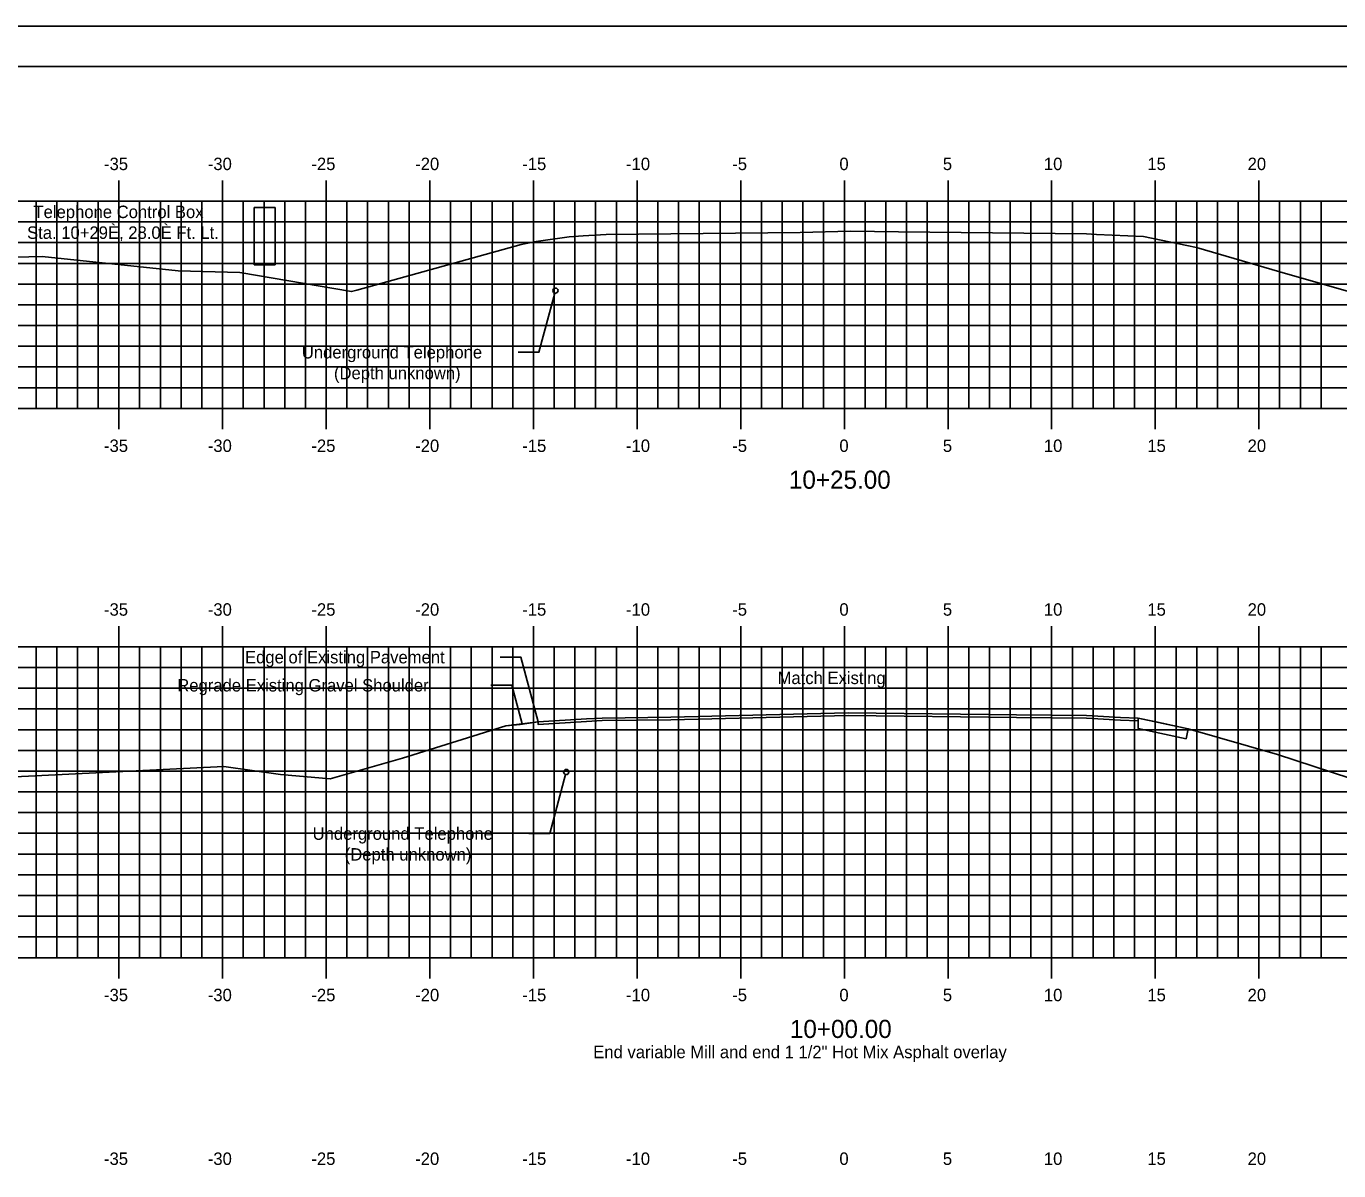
# Model space of a CAD drawing. Extents: x 2194738 to 2195190, y 863888 to 863998.
# Drawn here: x 2194880.8 to 2194944.1, y 863943.2 to 863998.4 of the extents above; entities that cross this region are included whole.
import ezdxf

# ---------------------------------------------------------------- set-up
doc = ezdxf.new("R2010")
doc.units = 0
for name, color, linetype in [('ANNOTATION', 7, 'Continuous'), ('BORDER', 7, 'Continuous'), ('H_V ANNOTATION', 7, 'Continuous'), ('MAJOR', 7, 'Continuous'), ('MINOR', 7, 'Continuous'), ('PLOT BOUNDARY', 7, 'Continuous'), ('S_Roadway_Centerline', 7, 'Continuous'), ('S_Utilities_Pole_Power', 7, 'Continuous'), ('TEMPLATE', 7, 'Continuous')]:
    doc.layers.add(name, color=color, linetype=linetype)

msp = doc.modelspace()

# ---------------------------------------------------------------- linework, layer by layer
at = {"layer": 'ANNOTATION'}
for points in [[(2194904.52, 863982.658), (2194905.52, 863982.658), (2194906.284, 863985.512)], [(2194903.646, 863967.946), (2194904.646, 863967.946), (2194904.646, 863967.946), (2194905.482, 863964.826)], [(2194903.204, 863966.589), (2194904.204, 863966.589), (2194904.204, 863966.589), (2194904.703, 863964.727)], [(2194905.04, 863959.432), (2194906.04, 863959.432), (2194906.804, 863962.286)]]:
    msp.add_lwpolyline(points, dxfattribs=at)
at = {"layer": 'BORDER'}
msp.add_lwpolyline([(2194845.256, 863891.446), (2195005.256, 863891.446), (2195005.256, 863996.446), (2194845.256, 863996.446)], close=True, dxfattribs=at)
at = {"layer": 'MAJOR'}
for p, q in [((2194885.256, 863990.948), (2194885.256, 863989.946)), ((2194890.256, 863990.948), (2194890.256, 863989.946)), ((2194895.256, 863990.948), (2194895.256, 863989.946)), ((2194900.256, 863990.948), (2194900.256, 863989.946)), ((2194905.256, 863990.948), (2194905.256, 863989.946)), ((2194910.256, 863990.948), (2194910.256, 863989.946)), ((2194915.256, 863990.948), (2194915.256, 863989.946)), ((2194920.256, 863990.948), (2194920.256, 863989.946)), ((2194925.256, 863990.948), (2194925.256, 863989.946)), ((2194930.256, 863990.948), (2194930.256, 863989.946)), ((2194935.256, 863990.948), (2194935.256, 863989.946)), ((2194940.256, 863990.948), (2194940.256, 863989.946)), ((2194850.256, 863989.946), (2194990.256, 863989.946)), ((2194885.256, 863979.946), (2194885.256, 863989.946)), ((2194890.256, 863979.946), (2194890.256, 863989.946)), ((2194895.256, 863979.946), (2194895.256, 863989.946)), ((2194900.256, 863979.946), (2194900.256, 863989.946)), ((2194905.256, 863979.946), (2194905.256, 863989.946)), ((2194910.256, 863979.946), (2194910.256, 863989.946)), ((2194915.256, 863979.946), (2194915.256, 863989.946)), ((2194920.256, 863979.946), (2194920.256, 863989.946)), ((2194925.256, 863979.946), (2194925.256, 863989.946)), ((2194930.256, 863979.946), (2194930.256, 863989.946)), ((2194935.256, 863979.946), (2194935.256, 863989.946)), ((2194940.256, 863979.946), (2194940.256, 863989.946)), ((2194850.256, 863984.946), (2194990.256, 863984.946)), ((2194850.256, 863979.946), (2194990.256, 863979.946)), ((2194885.256, 863978.944), (2194885.256, 863979.946)), ((2194890.256, 863978.944), (2194890.256, 863979.946)), ((2194895.256, 863978.944), (2194895.256, 863979.946)), ((2194900.256, 863978.944), (2194900.256, 863979.946)), ((2194905.256, 863978.944), (2194905.256, 863979.946)), ((2194910.256, 863978.944), (2194910.256, 863979.946)), ((2194915.256, 863978.944), (2194915.256, 863979.946)), ((2194920.256, 863978.944), (2194920.256, 863979.946)), ((2194925.256, 863978.944), (2194925.256, 863979.946)), ((2194930.256, 863978.944), (2194930.256, 863979.946)), ((2194935.256, 863978.944), (2194935.256, 863979.946)), ((2194940.256, 863978.944), (2194940.256, 863979.946)), ((2194885.256, 863969.448), (2194885.256, 863968.446)), ((2194890.256, 863969.448), (2194890.256, 863968.446)), ((2194895.256, 863969.448), (2194895.256, 863968.446)), ((2194900.256, 863969.448), (2194900.256, 863968.446)), ((2194905.256, 863969.448), (2194905.256, 863968.446)), ((2194910.256, 863969.448), (2194910.256, 863968.446)), ((2194915.256, 863969.448), (2194915.256, 863968.446)), ((2194920.256, 863969.448), (2194920.256, 863968.446)), ((2194925.256, 863969.448), (2194925.256, 863968.446)), ((2194930.256, 863969.448), (2194930.256, 863968.446)), ((2194935.256, 863969.448), (2194935.256, 863968.446)), ((2194940.256, 863969.448), (2194940.256, 863968.446)), ((2194850.256, 863968.446), (2194990.256, 863968.446)), ((2194885.256, 863953.446), (2194885.256, 863968.446)), ((2194890.256, 863953.446), (2194890.256, 863968.446)), ((2194895.256, 863953.446), (2194895.256, 863968.446)), ((2194900.256, 863953.446), (2194900.256, 863968.446)), ((2194905.256, 863953.446), (2194905.256, 863968.446)), ((2194910.256, 863953.446), (2194910.256, 863968.446)), ((2194915.256, 863953.446), (2194915.256, 863968.446)), ((2194920.256, 863953.446), (2194920.256, 863968.446)), ((2194925.256, 863953.446), (2194925.256, 863968.446)), ((2194930.256, 863953.446), (2194930.256, 863968.446)), ((2194935.256, 863953.446), (2194935.256, 863968.446)), ((2194940.256, 863953.446), (2194940.256, 863968.446)), ((2194850.256, 863963.446), (2194990.256, 863963.446)), ((2194850.256, 863958.446), (2194990.256, 863958.446)), ((2194850.256, 863953.446), (2194990.256, 863953.446)), ((2194885.256, 863952.444), (2194885.256, 863953.446)), ((2194890.256, 863952.444), (2194890.256, 863953.446)), ((2194895.256, 863952.444), (2194895.256, 863953.446)), ((2194900.256, 863952.444), (2194900.256, 863953.446)), ((2194905.256, 863952.444), (2194905.256, 863953.446)), ((2194910.256, 863952.444), (2194910.256, 863953.446)), ((2194915.256, 863952.444), (2194915.256, 863953.446)), ((2194920.256, 863952.444), (2194920.256, 863953.446)), ((2194925.256, 863952.444), (2194925.256, 863953.446)), ((2194930.256, 863952.444), (2194930.256, 863953.446)), ((2194935.256, 863952.444), (2194935.256, 863953.446)), ((2194940.256, 863952.444), (2194940.256, 863953.446))]:
    msp.add_line(p, q, dxfattribs=at)
at = {"layer": 'MINOR'}
for p, q in [((2194881.256, 863979.946), (2194881.256, 863989.946)), ((2194882.256, 863979.946), (2194882.256, 863989.946)), ((2194883.256, 863979.946), (2194883.256, 863989.946)), ((2194884.256, 863979.946), (2194884.256, 863989.946)), ((2194886.256, 863979.946), (2194886.256, 863989.946)), ((2194887.256, 863979.946), (2194887.256, 863989.946)), ((2194888.256, 863979.946), (2194888.256, 863989.946)), ((2194889.256, 863979.946), (2194889.256, 863989.946)), ((2194891.256, 863979.946), (2194891.256, 863989.946)), ((2194892.256, 863979.946), (2194892.256, 863989.946)), ((2194893.256, 863979.946), (2194893.256, 863989.946)), ((2194894.256, 863979.946), (2194894.256, 863989.946)), ((2194896.256, 863979.946), (2194896.256, 863989.946)), ((2194897.256, 863979.946), (2194897.256, 863989.946)), ((2194898.256, 863979.946), (2194898.256, 863989.946)), ((2194899.256, 863979.946), (2194899.256, 863989.946)), ((2194901.256, 863979.946), (2194901.256, 863989.946)), ((2194902.256, 863979.946), (2194902.256, 863989.946)), ((2194903.256, 863979.946), (2194903.256, 863989.946)), ((2194904.256, 863979.946), (2194904.256, 863989.946)), ((2194906.256, 863979.946), (2194906.256, 863989.946)), ((2194907.256, 863979.946), (2194907.256, 863989.946)), ((2194908.256, 863979.946), (2194908.256, 863989.946)), ((2194909.256, 863979.946), (2194909.256, 863989.946)), ((2194911.256, 863979.946), (2194911.256, 863989.946)), ((2194912.256, 863979.946), (2194912.256, 863989.946)), ((2194913.256, 863979.946), (2194913.256, 863989.946)), ((2194914.256, 863979.946), (2194914.256, 863989.946)), ((2194916.256, 863979.946), (2194916.256, 863989.946)), ((2194917.256, 863979.946), (2194917.256, 863989.946)), ((2194918.256, 863979.946), (2194918.256, 863989.946)), ((2194919.256, 863979.946), (2194919.256, 863989.946)), ((2194921.256, 863979.946), (2194921.256, 863989.946)), ((2194922.256, 863979.946), (2194922.256, 863989.946)), ((2194923.256, 863979.946), (2194923.256, 863989.946)), ((2194924.256, 863979.946), (2194924.256, 863989.946)), ((2194926.256, 863979.946), (2194926.256, 863989.946)), ((2194927.256, 863979.946), (2194927.256, 863989.946)), ((2194928.256, 863979.946), (2194928.256, 863989.946)), ((2194929.256, 863979.946), (2194929.256, 863989.946)), ((2194931.256, 863979.946), (2194931.256, 863989.946)), ((2194932.256, 863979.946), (2194932.256, 863989.946)), ((2194933.256, 863979.946), (2194933.256, 863989.946)), ((2194934.256, 863979.946), (2194934.256, 863989.946)), ((2194936.256, 863979.946), (2194936.256, 863989.946)), ((2194937.256, 863979.946), (2194937.256, 863989.946)), ((2194938.256, 863979.946), (2194938.256, 863989.946)), ((2194939.256, 863979.946), (2194939.256, 863989.946)), ((2194941.256, 863979.946), (2194941.256, 863989.946)), ((2194942.256, 863979.946), (2194942.256, 863989.946)), ((2194943.256, 863979.946), (2194943.256, 863989.946)), ((2194850.256, 863988.946), (2194990.256, 863988.946)), ((2194850.256, 863987.946), (2194990.256, 863987.946)), ((2194850.256, 863986.946), (2194990.256, 863986.946)), ((2194850.256, 863985.946), (2194990.256, 863985.946)), ((2194850.256, 863983.946), (2194990.256, 863983.946)), ((2194850.256, 863982.946), (2194990.256, 863982.946)), ((2194850.256, 863981.946), (2194990.256, 863981.946)), ((2194850.256, 863980.946), (2194990.256, 863980.946)), ((2194881.256, 863953.446), (2194881.256, 863968.446)), ((2194882.256, 863953.446), (2194882.256, 863968.446)), ((2194883.256, 863953.446), (2194883.256, 863968.446)), ((2194884.256, 863953.446), (2194884.256, 863968.446)), ((2194886.256, 863953.446), (2194886.256, 863968.446)), ((2194887.256, 863953.446), (2194887.256, 863968.446)), ((2194888.256, 863953.446), (2194888.256, 863968.446)), ((2194889.256, 863953.446), (2194889.256, 863968.446)), ((2194891.256, 863953.446), (2194891.256, 863968.446)), ((2194892.256, 863953.446), (2194892.256, 863968.446)), ((2194893.256, 863953.446), (2194893.256, 863968.446)), ((2194894.256, 863953.446), (2194894.256, 863968.446)), ((2194896.256, 863953.446), (2194896.256, 863968.446)), ((2194897.256, 863953.446), (2194897.256, 863968.446)), ((2194898.256, 863953.446), (2194898.256, 863968.446)), ((2194899.256, 863953.446), (2194899.256, 863968.446)), ((2194901.256, 863953.446), (2194901.256, 863968.446)), ((2194902.256, 863953.446), (2194902.256, 863968.446)), ((2194903.256, 863953.446), (2194903.256, 863968.446)), ((2194904.256, 863953.446), (2194904.256, 863968.446)), ((2194906.256, 863953.446), (2194906.256, 863968.446)), ((2194907.256, 863953.446), (2194907.256, 863968.446)), ((2194908.256, 863953.446), (2194908.256, 863968.446)), ((2194909.256, 863953.446), (2194909.256, 863968.446)), ((2194911.256, 863953.446), (2194911.256, 863968.446)), ((2194912.256, 863953.446), (2194912.256, 863968.446)), ((2194913.256, 863953.446), (2194913.256, 863968.446)), ((2194914.256, 863953.446), (2194914.256, 863968.446)), ((2194916.256, 863953.446), (2194916.256, 863968.446)), ((2194917.256, 863953.446), (2194917.256, 863968.446)), ((2194918.256, 863953.446), (2194918.256, 863968.446)), ((2194919.256, 863953.446), (2194919.256, 863968.446)), ((2194921.256, 863953.446), (2194921.256, 863968.446)), ((2194922.256, 863953.446), (2194922.256, 863968.446)), ((2194923.256, 863953.446), (2194923.256, 863968.446)), ((2194924.256, 863953.446), (2194924.256, 863968.446)), ((2194926.256, 863953.446), (2194926.256, 863968.446)), ((2194927.256, 863953.446), (2194927.256, 863968.446)), ((2194928.256, 863953.446), (2194928.256, 863968.446)), ((2194929.256, 863953.446), (2194929.256, 863968.446)), ((2194931.256, 863953.446), (2194931.256, 863968.446)), ((2194932.256, 863953.446), (2194932.256, 863968.446)), ((2194933.256, 863953.446), (2194933.256, 863968.446)), ((2194934.256, 863953.446), (2194934.256, 863968.446)), ((2194936.256, 863953.446), (2194936.256, 863968.446)), ((2194937.256, 863953.446), (2194937.256, 863968.446)), ((2194938.256, 863953.446), (2194938.256, 863968.446)), ((2194939.256, 863953.446), (2194939.256, 863968.446)), ((2194941.256, 863953.446), (2194941.256, 863968.446)), ((2194942.256, 863953.446), (2194942.256, 863968.446)), ((2194943.256, 863953.446), (2194943.256, 863968.446)), ((2194850.256, 863967.446), (2194990.256, 863967.446)), ((2194850.256, 863966.446), (2194990.256, 863966.446)), ((2194850.256, 863965.446), (2194990.256, 863965.446)), ((2194850.256, 863964.446), (2194990.256, 863964.446)), ((2194850.256, 863962.446), (2194990.256, 863962.446)), ((2194850.256, 863961.446), (2194990.256, 863961.446)), ((2194850.256, 863960.446), (2194990.256, 863960.446)), ((2194850.256, 863959.446), (2194990.256, 863959.446)), ((2194850.256, 863957.446), (2194990.256, 863957.446)), ((2194850.256, 863956.446), (2194990.256, 863956.446)), ((2194850.256, 863955.446), (2194990.256, 863955.446)), ((2194850.256, 863954.446), (2194990.256, 863954.446))]:
    msp.add_line(p, q, dxfattribs=at)
at = {"layer": 'PLOT BOUNDARY'}
msp.add_lwpolyline([(2194837.163, 863888.387), (2195007.163, 863888.387), (2195007.163, 863998.387), (2194837.163, 863998.387)], close=True, dxfattribs=at)
at = {"layer": 'S_Roadway_Centerline'}
for points in [[(2194850.256, 863987.118), (2194860.261, 863986.744), (2194881.56, 863987.272), (2194888.117, 863986.589), (2194891.093, 863986.502), (2194896.484, 863985.581), (2194896.738, 863985.651), (2194904.658, 863987.861), (2194905.389, 863987.998), (2194906.976, 863988.228), (2194907.657, 863988.272), (2194908.761, 863988.335), (2194918.129, 863988.439), (2194920.559, 863988.499), (2194922.869, 863988.473), (2194931.932, 863988.365), (2194932.412, 863988.339), (2194934.683, 863988.238), (2194936.777, 863987.806), (2194937.247, 863987.707), (2194941.272, 863986.538), (2194945.71, 863985.269)], [(2194850.256, 863960.77), (2194850.369, 863960.779), (2194861.52, 863961.766), (2194876.966, 863962.008), (2194890.309, 863962.671), (2194893.043, 863962.279), (2194895.447, 863962.079), (2194898.937, 863963.066), (2194903.925, 863964.628), (2194904.608, 863964.7), (2194905.482, 863964.826), (2194907.816, 863964.965), (2194908.574, 863965.008), (2194911.879, 863965.044), (2194920.431, 863965.259), (2194928.562, 863965.165), (2194931.945, 863965.125), (2194933.584, 863965.035), (2194934.433, 863964.997), (2194935.214, 863964.836), (2194936.848, 863964.491), (2194941.149, 863963.242), (2194946.41, 863961.523)]]:
    msp.add_lwpolyline(points, dxfattribs=at)
at = {"layer": 'S_Utilities_Pole_Power'}
msp.add_lwpolyline([(2194891.786, 863986.876), (2194892.786, 863986.876), (2194892.786, 863989.64), (2194891.786, 863989.64)], close=True, dxfattribs=at)
for centre in [(2194906.317, 863985.632), (2194906.837, 863962.406)]:
    msp.add_circle(centre, 0.125, dxfattribs=at)
at = {"layer": 'TEMPLATE'}
for p, q in [((2194903.925, 863964.628), (2194905.482, 863964.826)), ((2194934.433, 863964.997), (2194936.848, 863964.491)), ((2194936.848, 863964.491), (2194936.748, 863964.012))]:
    msp.add_line(p, q, dxfattribs=at)
for points in [[(2194905.482, 863964.826), (2194907.816, 863964.965), (2194908.574, 863965.008), (2194911.879, 863965.044), (2194920.431, 863965.259), (2194928.562, 863965.165), (2194931.945, 863965.125), (2194933.584, 863965.035), (2194934.433, 863964.997), (2194934.433, 863964.997)], [(2194905.482, 863964.826), (2194905.482, 863964.701), (2194907.816, 863964.84), (2194908.574, 863964.883), (2194911.879, 863964.919), (2194920.431, 863965.134), (2194928.562, 863965.04), (2194931.945, 863965), (2194933.584, 863964.91), (2194934.433, 863964.872), (2194934.433, 863964.997), (2194934.433, 863964.872)], [(2194934.433, 863964.997), (2194934.433, 863964.497), (2194936.748, 863964.012)]]:
    msp.add_lwpolyline(points, dxfattribs=at)

# ---------------------------------------------------------------- texts
at = {"layer": 'ANNOTATION'}
for s, p in [('Telephone Control Box', (2194881.132, 863989.131)), ('Sta. 10+29È, 28.0È Ft. Lt.', (2194880.823, 863988.129)), ('Underground Telephone', (2194894.08, 863982.358)), ('(Depth unknown)', (2194895.63, 863981.356)), ('Edge of Existing Pavement', (2194891.339, 863967.646)), ('Match Existing', (2194917.032, 863966.646)), ('Regrade Existing Gravel Shoulder', (2194888.07, 863966.289)), ('Underground Telephone', (2194894.6, 863959.132)), ('(Depth unknown)', (2194896.15, 863958.13)), ('End variable Mill and end 1 1/2" Hot Mix Asphalt overlay', (2194908.139, 863948.596))]:
    msp.add_text(s, height=0.6, dxfattribs=at).set_placement(p)
at = {"layer": 'H_V ANNOTATION'}
for s, height, p in [('-35', 0.6, (2194884.536, 863991.446)), ('-30', 0.6, (2194889.544, 863991.446)), ('-25', 0.6, (2194894.541, 863991.446)), ('-20', 0.6, (2194899.549, 863991.446)), ('-15', 0.6, (2194904.713, 863991.446)), ('-10', 0.6, (2194909.721, 863991.446)), ('-5', 0.6, (2194914.846, 863991.446)), ('0', 0.6, (2194920.015, 863991.446)), ('5', 0.6, (2194925.007, 863991.446)), ('10', 0.6, (2194929.881, 863991.446)), ('15', 0.6, (2194934.873, 863991.446)), ('20', 0.6, (2194939.71, 863991.446)), ('-35', 0.6, (2194884.536, 863977.846)), ('-30', 0.6, (2194889.544, 863977.846)), ('-25', 0.6, (2194894.541, 863977.846)), ('-20', 0.6, (2194899.549, 863977.846)), ('-15', 0.6, (2194904.713, 863977.846)), ('-10', 0.6, (2194909.721, 863977.846)), ('-5', 0.6, (2194914.846, 863977.846)), ('0', 0.6, (2194920.015, 863977.846)), ('5', 0.6, (2194925.007, 863977.846)), ('10', 0.6, (2194929.881, 863977.846)), ('15', 0.6, (2194934.873, 863977.846)), ('20', 0.6, (2194939.71, 863977.846)), ('10+25.00', 0.875, (2194917.579, 863976.071)), ('-35', 0.6, (2194884.536, 863969.946)), ('-30', 0.6, (2194889.544, 863969.946)), ('-25', 0.6, (2194894.541, 863969.946)), ('-20', 0.6, (2194899.549, 863969.946)), ('-15', 0.6, (2194904.713, 863969.946)), ('-10', 0.6, (2194909.721, 863969.946)), ('-5', 0.6, (2194914.846, 863969.946)), ('0', 0.6, (2194920.015, 863969.946)), ('5', 0.6, (2194925.007, 863969.946)), ('10', 0.6, (2194929.881, 863969.946)), ('15', 0.6, (2194934.873, 863969.946)), ('20', 0.6, (2194939.71, 863969.946)), ('-35', 0.6, (2194884.536, 863951.346)), ('-30', 0.6, (2194889.544, 863951.346)), ('-25', 0.6, (2194894.541, 863951.346)), ('-20', 0.6, (2194899.549, 863951.346)), ('-15', 0.6, (2194904.713, 863951.346)), ('-10', 0.6, (2194909.721, 863951.346)), ('-5', 0.6, (2194914.846, 863951.346)), ('0', 0.6, (2194920.015, 863951.346)), ('5', 0.6, (2194925.007, 863951.346)), ('10', 0.6, (2194929.881, 863951.346)), ('15', 0.6, (2194934.873, 863951.346)), ('20', 0.6, (2194939.71, 863951.346)), ('10+00.00', 0.875, (2194917.626, 863949.571)), ('-35', 0.6, (2194884.536, 863943.446)), ('-30', 0.6, (2194889.544, 863943.446)), ('-25', 0.6, (2194894.541, 863943.446)), ('-20', 0.6, (2194899.549, 863943.446)), ('-15', 0.6, (2194904.713, 863943.446)), ('-10', 0.6, (2194909.721, 863943.446)), ('-5', 0.6, (2194914.846, 863943.446)), ('0', 0.6, (2194920.015, 863943.446)), ('5', 0.6, (2194925.007, 863943.446)), ('10', 0.6, (2194929.881, 863943.446)), ('15', 0.6, (2194934.873, 863943.446)), ('20', 0.6, (2194939.71, 863943.446))]:
    msp.add_text(s, height=height, dxfattribs=at).set_placement(p)

doc.saveas('drawing.dxf')
